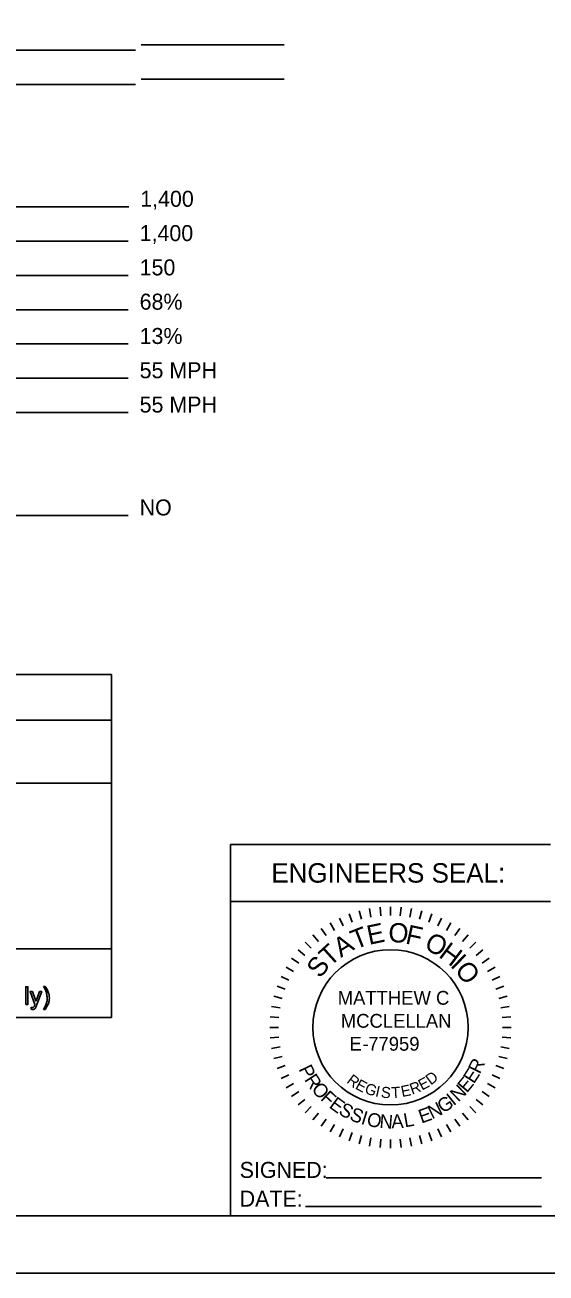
# Model space of a CAD drawing. Extents: x 0 to 34, y 0 to 22.
# Drawn here: x 7.23 to 11.79, y 0 to 10.92 of the extents above; entities that cross this region are included whole.
import ezdxf

# ---------------------------------------------------------------- set-up
doc = ezdxf.new("R2010")
doc.units = 0
for name, color, linetype in [('SH_Border', 7, 'Continuous'), ('SH_Cut_Line', 7, 'Continuous'), ('SH_Data', 7, 'Continuous'), ('TX_P_1', 7, 'Continuous')]:
    doc.layers.add(name, color=color, linetype=linetype)

msp = doc.modelspace()

# ---------------------------------------------------------------- linework, layer by layer
at = {"layer": 'SH_Border'}
msp.add_lwpolyline([(2, 21.5), (33.5, 21.5), (33.5, 0.5), (2, 0.5)], close=True, dxfattribs=at)
at = {"layer": 'SH_Cut_Line'}
msp.add_lwpolyline([(0, 0), (34, 0), (34, 22), (0, 22)], close=True, dxfattribs=at)
at = {"layer": 'SH_Data'}
for p, q in [((9.5, 10.743), (8.25, 10.743)), ((8.2, 10.697), (5.424, 10.697)), ((8.2, 10.397), (3.935, 10.397)), ((9.5, 10.443), (8.25, 10.443)), ((8.142, 9.327), (4.574, 9.327)), ((8.137, 9.027), (4.999, 9.027)), ((8.137, 8.727), (5.676, 8.727)), ((8.137, 8.427), (5.371, 8.427)), ((8.137, 8.127), (4.875, 8.127)), ((8.137, 7.827), (3.942, 7.827)), ((8.137, 7.527), (3.851, 7.527)), ((8.137, 6.627), (3.912, 6.627)), ((3.242, 5.235), (7.992, 5.235)), ((7.992, 2.235), (7.992, 5.235)), ((3.242, 4.835), (7.992, 4.835)), ((3.242, 4.285), (7.992, 4.285)), ((9.032, 0.5), (9.032, 3.75)), ((9.032, 3.75), (11.832, 3.75)), ((9.032, 3.25), (11.832, 3.25)), ((7.992, 2.835), (3.242, 2.835)), ((7.992, 2.235), (3.242, 2.235)), ((9.868, 0.832), (11.753, 0.832)), ((9.689, 0.581), (11.753, 0.581))]:
    msp.add_line(p, q, dxfattribs=at)
for points in [[(7.241, 2.35), (7.241, 2.504), (7.26, 2.504), (7.26, 2.35), (7.241, 2.35)], [(7.321, 2.35), (7.279, 2.462), (7.299, 2.462), (7.322, 2.397)], [(7.338, 2.397), (7.362, 2.462), (7.381, 2.462), (7.339, 2.348)], [(7.396, 2.507), (7.41, 2.507)], [(7.289, 2.307), (7.287, 2.325)], [(7.41, 2.305), (7.396, 2.305)]]:
    msp.add_lwpolyline(points, dxfattribs=at)
for points in [[(7.396, 2.305), (7.427, 2.355), (7.427, 2.406), (7.427, 2.426), (7.423, 2.445), (7.419, 2.461), (7.413, 2.475), (7.409, 2.485), (7.396, 2.507)], [(7.41, 2.507), (7.429, 2.48), (7.439, 2.454), (7.447, 2.431), (7.447, 2.406), (7.447, 2.378), (7.436, 2.351), (7.425, 2.325), (7.41, 2.305)], [(7.287, 2.325), (7.293, 2.323), (7.297, 2.323), (7.304, 2.323), (7.308, 2.325), (7.311, 2.328), (7.314, 2.331), (7.316, 2.334), (7.319, 2.345), (7.32, 2.347), (7.321, 2.35)], [(7.339, 2.348), (7.332, 2.33), (7.328, 2.323), (7.323, 2.314), (7.317, 2.309), (7.31, 2.305), (7.301, 2.305), (7.296, 2.305), (7.289, 2.307)], [(7.322, 2.397), (7.327, 2.385), (7.33, 2.372), (7.334, 2.384), (7.338, 2.397)]]:
    msp.add_open_spline(points, degree=3, dxfattribs=at)
at = {"layer": 'TX_P_1'}
for points in [[(10.178, 3.095), (10.158, 3.168)], [(10.261, 3.114), (10.248, 3.188)], [(10.346, 3.125), (10.34, 3.2)], [(10.432, 3.204), (10.432, 3.129)], [(10.517, 3.125), (10.524, 3.2)], [(10.602, 3.114), (10.615, 3.188)], [(10.685, 3.095), (10.705, 3.168)], [(9.942, 2.997), (9.904, 3.063)], [(10.017, 3.037), (9.986, 3.105)], [(10.096, 3.07), (10.071, 3.141)], [(10.767, 3.07), (10.793, 3.141)], [(10.846, 3.037), (10.878, 3.105)], [(10.922, 2.997), (10.959, 3.063)], [(9.802, 2.899), (9.753, 2.957)], [(9.869, 2.952), (9.826, 3.013)], [(10.994, 2.952), (11.037, 3.013)], [(11.062, 2.899), (11.11, 2.957)], [(9.739, 2.842), (9.685, 2.895)], [(11.125, 2.842), (11.178, 2.895)], [(9.629, 2.711), (9.567, 2.754)], [(9.681, 2.779), (9.623, 2.827)], [(11.182, 2.779), (11.24, 2.827)], [(11.234, 2.711), (11.296, 2.754)], [(9.583, 2.639), (9.518, 2.676)], [(11.28, 2.639), (11.346, 2.676)], [(9.543, 2.563), (9.475, 2.595)], [(11.32, 2.563), (11.388, 2.595)], [(9.485, 2.402), (9.412, 2.422)], [(9.511, 2.484), (9.44, 2.51)], [(11.353, 2.484), (11.423, 2.51)], [(11.378, 2.402), (11.451, 2.422)], [(9.466, 2.319), (9.392, 2.332)], [(11.397, 2.319), (11.471, 2.332)], [(9.455, 2.234), (9.38, 2.241)], [(11.408, 2.234), (11.483, 2.241)], [(9.452, 2.149), (9.376, 2.149)], [(11.412, 2.149), (11.487, 2.149)], [(9.455, 2.063), (9.38, 2.057)], [(9.466, 1.979), (9.392, 1.965)], [(11.397, 1.979), (11.471, 1.965)], [(11.408, 2.063), (11.483, 2.057)], [(9.485, 1.895), (9.412, 1.876)], [(11.378, 1.895), (11.451, 1.876)], [(9.511, 1.814), (9.44, 1.788)], [(11.353, 1.814), (11.423, 1.788)], [(9.543, 1.735), (9.475, 1.703)], [(9.583, 1.659), (9.518, 1.621)], [(11.28, 1.659), (11.346, 1.621)], [(11.32, 1.735), (11.388, 1.703)], [(9.629, 1.587), (9.567, 1.543)], [(11.234, 1.587), (11.296, 1.543)], [(9.681, 1.519), (9.623, 1.47)], [(9.739, 1.456), (9.685, 1.402)], [(11.125, 1.456), (11.178, 1.402)], [(11.182, 1.519), (11.24, 1.47)], [(9.802, 1.398), (9.753, 1.34)], [(9.869, 1.346), (9.826, 1.284)], [(10.994, 1.346), (11.037, 1.284)], [(11.062, 1.398), (11.11, 1.34)], [(9.942, 1.3), (9.904, 1.235)], [(10.017, 1.26), (9.986, 1.192)], [(10.096, 1.228), (10.071, 1.157)], [(10.178, 1.202), (10.158, 1.129)], [(10.685, 1.202), (10.705, 1.129)], [(10.767, 1.228), (10.793, 1.157)], [(10.846, 1.26), (10.878, 1.192)], [(10.922, 1.3), (10.959, 1.235)], [(10.261, 1.184), (10.248, 1.109)], [(10.346, 1.172), (10.34, 1.097)], [(10.432, 1.169), (10.432, 1.093)], [(10.517, 1.172), (10.524, 1.097)], [(10.602, 1.184), (10.615, 1.109)]]:
    msp.add_lwpolyline(points, dxfattribs=at)
for start, end in [(0, 180), (180, 0)]:
    msp.add_arc((10.432, 2.149), 0.679, start, end, dxfattribs=at)

# ---------------------------------------------------------------- texts
at = {"layer": 'SH_Data'}
for s, height, p in [('1,400', 0.14, (8.242, 9.327)), ('1,400', 0.14, (8.237, 9.027)), ('150', 0.14, (8.237, 8.727)), ('68%', 0.14, (8.237, 8.427)), ('13%', 0.14, (8.237, 8.127)), ('55 MPH', 0.14, (8.237, 7.827)), ('55 MPH', 0.14, (8.237, 7.527)), ('NO', 0.14, (8.237, 6.627)), ('ENGINEERS SEAL:', 0.17, (9.389, 3.415)), ('SIGNED:', 0.14, (9.112, 0.832)), ('DATE:', 0.14, (9.112, 0.581))]:
    msp.add_text(s, height=height, dxfattribs=at).set_placement(p)
at = {"layer": 'TX_P_1'}
for s, height, rotation, p in [('E', 0.169, 11.7851, (10.244, 2.87)), ('O', 0.169, 357.8702, (10.411, 2.895)), ('T', 0.169, 21.3308, (10.124, 2.828)), ('F', 0.169, 347.6665, (10.555, 2.884)), ('O', 0.169, 333.7516, (10.718, 2.838)), ('T', 0.169, 42.2436, (9.902, 2.674)), ('A', 0.169, 31.7875, (9.998, 2.756)), ('H', 0.169, 323.0924, (10.845, 2.77)), ('S', 0.169, 52.2449, (9.817, 2.571)), ('I', 0.169, 315.8791, (10.948, 2.686)), ('O', 0.169, 308.214, (10.987, 2.647)), ('R', 0.121, 63.8926, (11.213, 1.735)), ('P', 0.121, 296.106, (9.626, 1.785)), ('R', 0.121, 302.9019, (9.674, 1.692)), ('D', 0.0965, 36.9716, (10.784, 1.64)), ('E', 0.121, 57.2495, (11.161, 1.649)), ('O', 0.121, 310.0944, (9.734, 1.606)), ('R', 0.0965, 322.8855, (10.041, 1.669)), ('E', 0.0965, 331.3777, (10.117, 1.616)), ('G', 0.0965, 340.1488, (10.198, 1.576)), ('I', 0.0965, 347.1744, (10.293, 1.546)), ('E', 0.0965, 11.3558, (10.533, 1.539)), ('R', 0.0965, 19.8478, (10.62, 1.56)), ('E', 0.0965, 28.34, (10.707, 1.595)), ('N', 0.121, 43.9937, (11.024, 1.492)), ('E', 0.121, 50.7591, (11.1, 1.57)), ('F', 0.121, 317.1346, (9.812, 1.519)), ('E', 0.121, 323.6251, (9.887, 1.453)), ('S', 0.0965, 354.0571, (10.344, 1.536)), ('T', 0.0965, 2.8636, (10.44, 1.53)), ('G', 0.121, 33.3966, (10.891, 1.393)), ('I', 0.121, 38.7569, (10.983, 1.458)), ('S', 0.121, 330.3902, (9.969, 1.395)), ('S', 0.121, 337.4303, (10.065, 1.344)), ('E', 0.121, 19.4693, (10.702, 1.307)), ('N', 0.121, 26.2345, (10.795, 1.343)), ('I', 0.121, 342.6684, (10.166, 1.306)), ('O', 0.121, 348.1798, (10.217, 1.291)), ('N', 0.121, 355.4948, (10.332, 1.27)), ('A', 0.121, 2.8095, (10.441, 1.265)), ('L', 0.121, 9.8497, (10.557, 1.274))]:
    msp.add_text(s, height=height, rotation=rotation, dxfattribs=at).set_placement(p)
for s, height, p in [('MATTHEW C ', 0.1206, (9.97, 2.347)), ('MCCLELLAN', 0.1206, (9.997, 2.146)), ('E', 0.121, (10.073, 1.945)), ('-', 0.121, (10.188, 1.945)), ('77959', 0.1206, (10.237, 1.945))]:
    msp.add_text(s, height=height, dxfattribs=at).set_placement(p)

doc.saveas('drawing.dxf')
